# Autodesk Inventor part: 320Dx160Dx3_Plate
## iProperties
Shininess: 64.0
Length Units: 11269
Angle Units: 11279
Time Units: 11290
Mass Units: 11283
Length Display Precision: 3
Angle Display Precision: 2
Compacted: True
Part Number: 320Dx160Dx3_Plate
Document SubType Name: Modeling
Created: 2004-07
Designer: John Blackburn
Manufacturer: Standard
Standards Organization: Custom
Material: Stainless Steel, 440C
Density: 0.0
Volumn: 0.0
Area: 0.0
PropertySet Name: Model Information
Control State: 0
Master: False
Checked Out: False
Author: John Blackburn
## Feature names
1. Extrusion1
